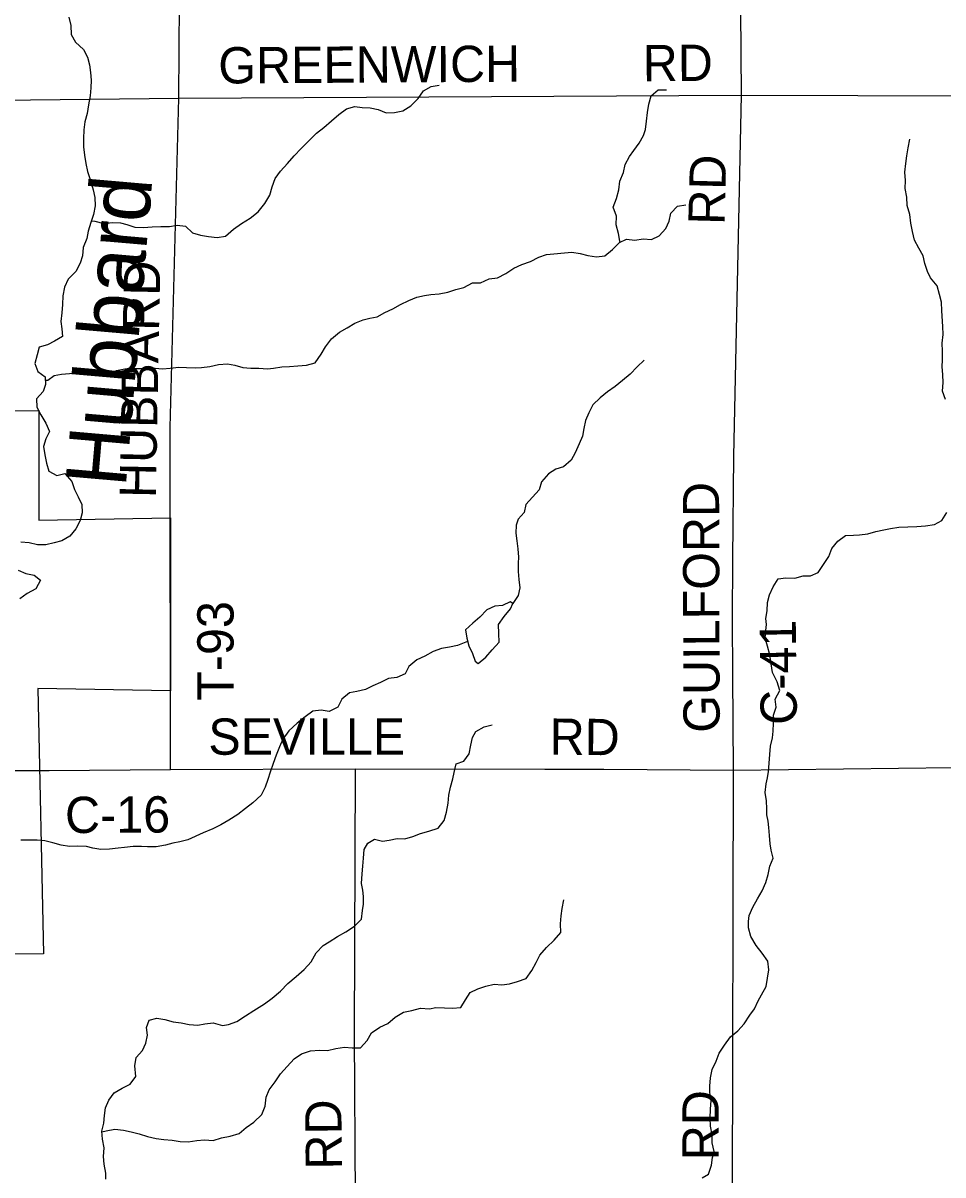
# Model space of a CAD drawing. Extents: x 1985906 to 2277390, y 930619 to 1324581.
# Drawn here: x 2146803 to 2154411, y 1093746 to 1103268 of the extents above; entities that cross this region are included whole.
import ezdxf

# ---------------------------------------------------------------- set-up
doc = ezdxf.new("R2010")
doc.units = 0
for name, color, linetype in [('GM_X_City_Street', 7, 'Continuous'), ('GM_X_Corporation', 7, 'Continuous'), ('GM_X_County_Road', 7, 'Continuous'), ('GM_X_County_Road_Text', 7, 'Continuous'), ('GM_X_Minor_Lake', 7, 'Continuous'), ('GM_X_Minor_River', 7, 'Continuous'), ('GM_X_Minor_River_Text', 7, 'Continuous'), ('GM_X_Township_Road', 7, 'Continuous'), ('GM_X_Township_Road_Text', 7, 'Continuous')]:
    doc.layers.add(name, color=color, linetype=linetype)

msp = doc.modelspace()

# ---------------------------------------------------------------- linework, layer by layer
at = {"layer": 'GM_X_City_Street'}
msp.add_lwpolyline([(2144906.3, 1097104.6), (2145782.8, 1097089), (2145830.7, 1097088.2), (2146944.6, 1097090.1), (2147019.2, 1097090.6)], dxfattribs=at)
at = {"layer": 'GM_X_Corporation'}
msp.add_lwpolyline([(2146630.7, 1100061.2), (2146933.1, 1100066.5), (2146933.1, 1099158.3), (2148022.9, 1099177.3), (2148022.9, 1097747.3), (2146924.6, 1097766.5), (2146973.3, 1095572.8), (2145031.8, 1095556.9)], dxfattribs=at)
at = {"layer": 'GM_X_County_Road'}
for points in [[(2152678.4, 1097092.6), (2152673.3, 1097881.4), (2152670.3, 1098337.9), (2152673.1, 1098838.5), (2152681.6, 1099687.5), (2152744, 1102670.9), (2152734.4, 1104084), (2152737.7, 1104462.8)], [(2145636.5, 1102618.6), (2148092.1, 1102646.5), (2152744, 1102670.9), (2157560, 1102659.5), (2158937.6, 1102692.5), (2161297.2, 1102684.6), (2161486.2, 1102684.9)], [(2147019.2, 1097090.6), (2148022.9, 1097097.3), (2149553.3, 1097103.6), (2151117.8, 1097100.1), (2151606, 1097099.4), (2152678.4, 1097092.6), (2156317.3, 1097135), (2156707.4, 1097137.6), (2156889.5, 1097136.8), (2157593.3, 1097149.9), (2159274.3, 1097152.9), (2159744.4, 1097158), (2160686.6, 1097174.4), (2161805, 1097183.9), (2162757.2, 1097196.3)]]:
    msp.add_lwpolyline(points, dxfattribs=at)
at = {"layer": 'GM_X_Minor_Lake'}
for points in [[(2150853.3, 1098471.1), (2150832.1, 1098484.6), (2150768.4, 1098453.7), (2150704.4, 1098448.9), (2150638.6, 1098418), (2150581.3, 1098357.2), (2150523.8, 1098308.4), (2150462.4, 1098251.6), (2150473.2, 1098183.6), (2150490, 1098119.7), (2150518.8, 1098057.9), (2150541.7, 1097992.1)], [(2150853.4, 1098471.1), (2150832.1, 1098484.6), (2150768.4, 1098453.7), (2150704.4, 1098448.9), (2150638.6, 1098418), (2150581.3, 1098357.2), (2150523.8, 1098308.4), (2150462.4, 1098251.6), (2150473.2, 1098183.6), (2150490, 1098119.7), (2150518.8, 1098057.9), (2150541.7, 1097992.1)], [(2150541.7, 1097992.1), (2150565.9, 1097974.4), (2150631.4, 1098027.3), (2150682.7, 1098088), (2150742, 1098150.9), (2150737.2, 1098222.9), (2150736.3, 1098295.1), (2150781.5, 1098361.7), (2150834.8, 1098426.5), (2150853.3, 1098471.1)], [(2150541.7, 1097992.1), (2150565.9, 1097974.4), (2150631.4, 1098027.3), (2150682.7, 1098088), (2150742, 1098150.9), (2150737.2, 1098222.9), (2150736.3, 1098295.1), (2150781.5, 1098361.7), (2150834.8, 1098426.5), (2150853.1, 1098470.8)]]:
    msp.add_lwpolyline(points, dxfattribs=at)
at = {"layer": 'GM_X_Minor_River'}
for points in [[(2147180.5, 1103316.9), (2147197, 1103246.9), (2147201.5, 1103172.8), (2147238, 1103108.9), (2147302.5, 1103049.2), (2147336.9, 1102987.4), (2147351.4, 1102923.3), (2147361.8, 1102859.3), (2147366.2, 1102797.2), (2147364.7, 1102733.1), (2147359.1, 1102666.9), (2147345.6, 1102592.7), (2147332, 1102520.5), (2147314.5, 1102452.3), (2147306.9, 1102384.1), (2147303.4, 1102314), (2147303.8, 1102243.8), (2147310.3, 1102175.8), (2147322.8, 1102107.7), (2147337.2, 1102041.7), (2147361.8, 1101965.8), (2147384.3, 1101889.8), (2147396.7, 1101825.8), (2147399.2, 1101757.6), (2147385.7, 1101685.4), (2147364.1, 1101619.2), (2147340.5, 1101548.9), (2147330.9, 1101486.7), (2147301.4, 1101412.4), (2147295.8, 1101344.2), (2147276.2, 1101282), (2147240.6, 1101213.6), (2147177, 1101151.1), (2147145.4, 1101084.8), (2147131.8, 1101012.6), (2147130.3, 1100940.4), (2147124.8, 1100872.3), (2147115.2, 1100800.1), (2147123.6, 1100740), (2147128.1, 1100675.9), (2147064.2, 1100639.5), (2147004.4, 1100609), (2146936.4, 1100588.5), (2146920.8, 1100524.3), (2146901.3, 1100454), (2146925.7, 1100388.1), (2146986.1, 1100342.4), (2146988.5, 1100280.3), (2146968.9, 1100222.1), (2146913.2, 1100161.6), (2146915.7, 1100093.5), (2146950.1, 1100029.6)], [(2147368.6, 1101633), (2147398.1, 1101629.4), (2147470.3, 1101609.9), (2147542.3, 1101620.4), (2147610.4, 1101616.8), (2147660.6, 1101603.1), (2147726.8, 1101579.5), (2147798.9, 1101578), (2147871, 1101582.5), (2147943, 1101585), (2148013.1, 1101585.5), (2148077.1, 1101597.9), (2148145.3, 1101588.3), (2148205.7, 1101532.6), (2148269.9, 1101515.1), (2148336.1, 1101503.5), (2148408.2, 1101495.9), (2148476.2, 1101506.4), (2148543.9, 1101565), (2148609.7, 1101611.5), (2148681.5, 1101654.1), (2148747.2, 1101708.6), (2148802.8, 1101775.1), (2148844.4, 1101845.5), (2148864, 1101913.7), (2148887.6, 1101984), (2148933.2, 1102044.4), (2148988.9, 1102106.9), (2149046.5, 1102169.4), (2149104.2, 1102229.9), (2149171.8, 1102300.5), (2149229.5, 1102359), (2149291.3, 1102403.4), (2149355, 1102460), (2149414.7, 1102512.5), (2149478.5, 1102559), (2149546.4, 1102577.5), (2149606.6, 1102569.8), (2149674.7, 1102566.3), (2149738.8, 1102552.7), (2149805.1, 1102525.1), (2149875.2, 1102529.6), (2149943.2, 1102542), (2150009, 1102584.6), (2150070.6, 1102643.1), (2150116.3, 1102707.5), (2150178.1, 1102744), (2150244.1, 1102754.4)], [(2151742.4, 1101457.6), (2151738.6, 1101464.2), (2151728.1, 1101528.2), (2151709.6, 1101600.2), (2151711.2, 1101672.4), (2151684.6, 1101746.3), (2151712.2, 1101818.6), (2151731.7, 1101888.9), (2151739.3, 1101961.1), (2151768.8, 1102031.4), (2151782.4, 1102099.6), (2151818, 1102163.9), (2151855.7, 1102214.3), (2151899.4, 1102274.7), (2151935, 1102339), (2151950.7, 1102389.2), (2151960.2, 1102457.4), (2151967.8, 1102527.6), (2151977.3, 1102597.8), (2151996.9, 1102666), (2152054.6, 1102716.5), (2152124.7, 1102714.9)], [(2154430.7, 1100155.9), (2154408.2, 1100225.9), (2154411.7, 1100298.1), (2154409.3, 1100360.1), (2154404.8, 1100430.2), (2154408.5, 1100480.4), (2154406, 1100554.5), (2154403.5, 1100622.6), (2154413.1, 1100694.8), (2154410.6, 1100760.9), (2154401.8, 1100889), (2154399.3, 1100961.1), (2154382.8, 1101023.1), (2154364.3, 1101095.1), (2154307.8, 1101162.9), (2154283.4, 1101214.8), (2154261, 1101280.8), (2154246.5, 1101344.8), (2154212.1, 1101406.6), (2154175.6, 1101474.5), (2154159.1, 1101544.5), (2154144.6, 1101614.6), (2154136.1, 1101686.6), (2154115.6, 1101758.6), (2154113.1, 1101828.7), (2154098.6, 1101900.7), (2154102.2, 1101966.9), (2154095.7, 1102035), (2154103.3, 1102107.1), (2154112.9, 1102171.3), (2154122.4, 1102237.5), (2154136, 1102307.7)], [(2146987.2, 1100315.7), (2147008.3, 1100316.5), (2147060.1, 1100354.9), (2147120.1, 1100365.4), (2147186.2, 1100371.8), (2147236.2, 1100374.1), (2147306.4, 1100366.6), (2147374.4, 1100377.1), (2147442.5, 1100367.5), (2147510.6, 1100364), (2147576.5, 1100396.5), (2147644.5, 1100408.9), (2147708.6, 1100411.4), (2147772.6, 1100411.8), (2147822.7, 1100414.1), (2147894.7, 1100416.6), (2147956.9, 1100409), (2148020.9, 1100415.5), (2148090.9, 1100424), (2148155, 1100420.4), (2148227.2, 1100416.9), (2148279.2, 1100421.2), (2148347.2, 1100429.7), (2148419.2, 1100444.2), (2148493.3, 1100450.7), (2148553.4, 1100441.1), (2148619.6, 1100421.5), (2148685.7, 1100413.9), (2148751.8, 1100414.4), (2148823.9, 1100410.8), (2148874, 1100415.2), (2148944, 1100425.7), (2149008, 1100430.1), (2149076.1, 1100434.6), (2149148.2, 1100439.1), (2149220.1, 1100459.6), (2149267.7, 1100530), (2149305.4, 1100590.4), (2149352.9, 1100658.8), (2149420.7, 1100713.4), (2149484.5, 1100749.9), (2149546.3, 1100788.3), (2149616.2, 1100814.9), (2149670.2, 1100829.2), (2149732.2, 1100839.7), (2149794.1, 1100874.1), (2149860, 1100904.6), (2149925.8, 1100941.1), (2149993.6, 1100975.7), (2150059.6, 1101002.1), (2150123.5, 1101016.6), (2150175.6, 1101023), (2150243.6, 1101029.4), (2150315.6, 1101043.9), (2150383.5, 1101064.4), (2150449.5, 1101080.9), (2150519.3, 1101119.4), (2150587.4, 1101119.9), (2150657.3, 1101152.4), (2150727.3, 1101162.9), (2150797.2, 1101197.4), (2150861, 1101241.9), (2150928.8, 1101272.4), (2150998.8, 1101296.9), (2151068.6, 1101333.5), (2151132.6, 1101353.9), (2151342.7, 1101373.4), (2151410.8, 1101363.8), (2151475, 1101346.2), (2151545.2, 1101334.7), (2151615.2, 1101343.2), (2151679, 1101395.7), (2151734.6, 1101454.1), (2151794.5, 1101480.6), (2151862.7, 1101473), (2151930.7, 1101483.5), (2152000.8, 1101478), (2152064.7, 1101508.4), (2152118.3, 1101570.9), (2152146, 1101631.2), (2152161.6, 1101697.4), (2152215.2, 1101753.9), (2152285.3, 1101766.4)], [(2151939.4, 1100481.8), (2151881.7, 1100427.3), (2151824, 1100366.9), (2151760.2, 1100314.3), (2151700.5, 1100263.9), (2151636.7, 1100219.3), (2151575, 1100170.9), (2151515.3, 1100112.3), (2151481.7, 1100046), (2151456.1, 1099981.7), (2151440.5, 1099915.5), (2151428.9, 1099853.3), (2151401.3, 1099789), (2151369.7, 1099716.7), (2151336.1, 1099654.4), (2151272.4, 1099599.8), (2151210.4, 1099579.4), (2151148.6, 1099542.9), (2151091, 1099474.4), (2151071.4, 1099410.2), (2151015.8, 1099347.7), (2150960.1, 1099287.2), (2150948.5, 1099223), (2150896.8, 1099166.6), (2150881.1, 1099116.4), (2150879.5, 1099052.3), (2150888, 1098988.2), (2150894.4, 1098922.1), (2150900.9, 1098854.1), (2150899.2, 1098803.9), (2150897.7, 1098733.8), (2150904.1, 1098667.8), (2150910.6, 1098599.7), (2150897, 1098535.5), (2150853.4, 1098471.1)], [(2146950.1, 1100029.6), (2146990.7, 1099961.8), (2147023.2, 1099891.9), (2146991.5, 1099831.6), (2146971.9, 1099767.3), (2146982.4, 1099699.3), (2146996.9, 1099629.2), (2147017.3, 1099563.3), (2147083.7, 1099527.7), (2147149.6, 1099544.1), (2147206.1, 1099478.4), (2147228.6, 1099412.4), (2147259, 1099352.5), (2147289.5, 1099288.6), (2147292, 1099218.5), (2147276.4, 1099156.3), (2147240.8, 1099085.9), (2147191.1, 1099025.5), (2147123.3, 1098989), (2147059.3, 1098970.5), (2146991.4, 1098954), (2146923.3, 1098953.6), (2146853.1, 1098971.1), (2146784.9, 1098976.7)], [(2153857.2, 1099066.2), (2153921.2, 1099078.7), (2153977.2, 1099091.1), (2154047.2, 1099099.6), (2154121.3, 1099104.1), (2154195.3, 1099106.6), (2154267.4, 1099111.1), (2154341.4, 1099121.6), (2154401.3, 1099156), (2154442.9, 1099222.4)], [(2152418.9, 1093721.3), (2152472.8, 1093751.7), (2152496.3, 1093826), (2152503.9, 1093890.2), (2152517.6, 1093940.4), (2152501.1, 1094010.4), (2152502.7, 1094076.5), (2152488.2, 1094148.5), (2152485.7, 1094216.6), (2152487.2, 1094288.8), (2152494.8, 1094360.9), (2152484.3, 1094429), (2152481.9, 1094481.1), (2152487.5, 1094549.2), (2152503.1, 1094617.4), (2152534.6, 1094685.8), (2152560.2, 1094752.1), (2152603.9, 1094818.5), (2152653.5, 1094886.9), (2152713.2, 1094937.4), (2152766.9, 1094995.9), (2152814.5, 1095066.3), (2152852.1, 1095120.7), (2152883.8, 1095185), (2152911.5, 1095235.2), (2152949.1, 1095303.6), (2152960.6, 1095371.8), (2152972.2, 1095442), (2152963.7, 1095512.1), (2152915.2, 1095579.9), (2152866.7, 1095643.7), (2152822.1, 1095717.5), (2152803.6, 1095789.5), (2152803.3, 1095841.6), (2152809, 1095891.7), (2152838.5, 1095960), (2152876.1, 1096028.4), (2152915.8, 1096094.8), (2152945.3, 1096163.1), (2152964.9, 1096229.3), (2152980.5, 1096297.6), (2153008.1, 1096365.9), (2152989.6, 1096431.8), (2152981.3, 1096483.9), (2152976.8, 1096552), (2152972.3, 1096618.1), (2152966, 1096670.1), (2152955.6, 1096722.1), (2152955.3, 1096772.2), (2152950.9, 1096838.3), (2152940.4, 1096908.3), (2152947.9, 1096978.5), (2152959.6, 1097028.7), (2152967.3, 1097080.8), (2152974.8, 1097151), (2152980.3, 1097223.1), (2152985.9, 1097289.3), (2153001.5, 1097359.5), (2153007.1, 1097415.7), (2153010.7, 1097479.8), (2153008.2, 1097547.9), (2153031.8, 1097614.2), (2153023.4, 1097678.2), (2153062.9, 1097750.6), (2153040.4, 1097822.6), (2153001.9, 1097898.5), (2152991.4, 1097972.5), (2152978.9, 1098046.6), (2152960.4, 1098116.6), (2152939.9, 1098182.5), (2152947.5, 1098246.7), (2152951.2, 1098296.8), (2152946.8, 1098346.9), (2152956.4, 1098409.1), (2152960, 1098477.2), (2152977.6, 1098541.4), (2153007.2, 1098607.7), (2153048.8, 1098674.1), (2153112.8, 1098682.6), (2153184.9, 1098679.1), (2153254.9, 1098699.6), (2153314.9, 1098697.9), (2153378.8, 1098726.4), (2153424.4, 1098792.8), (2153468.1, 1098859.2), (2153491.7, 1098923.5), (2153541.3, 1098986), (2153605.1, 1099032.5), (2153671.1, 1099034.9), (2153721.2, 1099037.3), (2153789.2, 1099045.7), (2153857.2, 1099066.2)], [(2146762.5, 1098744.1), (2146826.7, 1098718.5), (2146894.9, 1098702.9), (2146947.2, 1098663.2), (2146909.7, 1098590.8), (2146835.8, 1098552.3), (2146776.1, 1098509.8)], [(2150479.8, 1098156.1), (2150397.1, 1098121.4), (2150329.1, 1098108.9), (2150263.1, 1098098.5), (2150195.2, 1098072), (2150125.4, 1098033.4), (2150059.5, 1098002.9), (2149993.8, 1097950.4), (2149962.2, 1097888.1), (2149894.3, 1097859.6), (2149826.2, 1097851.1), (2149760.4, 1097816.6), (2149696.5, 1097790.1), (2149634.6, 1097759.7), (2149564.6, 1097741.2), (2149502.6, 1097732.7), (2149440.9, 1097680.2), (2149405.3, 1097613.9), (2149333.4, 1097577.3), (2149267.3, 1097588.9), (2149199.3, 1097580.4), (2149135.5, 1097533.9), (2149069.8, 1097479.4), (2149002.1, 1097416.8), (2148952.5, 1097348.4), (2148922.9, 1097286.1), (2148895.3, 1097215.8), (2148871.7, 1097147.5), (2148846.2, 1097075.2), (2148826.6, 1097015), (2148805, 1096950.7), (2148771.3, 1096886.4), (2148703.7, 1096821.8), (2148641.9, 1096775.3), (2148578.2, 1096726.8), (2148504.4, 1096680.2), (2148438.6, 1096639.7), (2148372.7, 1096607.2), (2148292.8, 1096574.6), (2148167, 1096517.7), (2148101.1, 1096499.2), (2148043.1, 1096488.8), (2147981.1, 1096472.4), (2147903.1, 1096457.8), (2147833, 1096457.3), (2147782.9, 1096461), (2147714.8, 1096462.6), (2147640.8, 1096452), (2147588.8, 1096447.7), (2147518.8, 1096439.2), (2147446.7, 1096436.7), (2147380.5, 1096448.3), (2147328.4, 1096460), (2147256.3, 1096463.5), (2147186.2, 1096461), (2147118, 1096472.6), (2147049.8, 1096492.2), (2146983.6, 1096507.7), (2146919.5, 1096513.3), (2146849.4, 1096512.8), (2146785.4, 1096514.4)], [(2147488.9, 1093712.3), (2147486.5, 1093762.3), (2147474, 1093834.4), (2147467.6, 1093898.5), (2147475.1, 1093970.6), (2147460.7, 1094040.7), (2147454.2, 1094108.7), (2147471.8, 1094175), (2147475.4, 1094237.1), (2147484.9, 1094301.3), (2147512.6, 1094365.6), (2147556.2, 1094426), (2147622, 1094464.5), (2147687.9, 1094497), (2147735.5, 1094559.4), (2147728.9, 1094647.5), (2147738.5, 1094717.7), (2147790.2, 1094776.1), (2147817.8, 1094836.4), (2147833.4, 1094902.6), (2147825, 1094964.7), (2147846.6, 1095024.9), (2147908.6, 1095041.4), (2147976.7, 1095031.8), (2148044.9, 1095012.3), (2148111.1, 1095002.7), (2148177.2, 1094991.1), (2148247.4, 1094983.6), (2148305.3, 1094996), (2148375.4, 1095002.5), (2148451.6, 1094982.9), (2148501.6, 1094989.3), (2148571.6, 1095013.8), (2148643.3, 1095060.4), (2148711.1, 1095104.9), (2148798.9, 1095159.6), (2148864.6, 1095208.1), (2148932.3, 1095264.6), (2148992, 1095329.1), (2149061.7, 1095385.7), (2149127.4, 1095444.3), (2149187, 1095508.8), (2149228.6, 1095581.2), (2149284.2, 1095643.7), (2149336.1, 1095674.1), (2149403.9, 1095716.6), (2149473.7, 1095755.1), (2149543.5, 1095803.7), (2149603.2, 1095860.2), (2149610.7, 1095932.3), (2149618.4, 1095984.5), (2149620, 1096048.6), (2149613.6, 1096100.6), (2149603.2, 1096156.7), (2149608.7, 1096234.9), (2149614.3, 1096299), (2149617.9, 1096365.1), (2149623.4, 1096435.3), (2149655.1, 1096487.6), (2149710.9, 1096522), (2149777.1, 1096506.5), (2149831.1, 1096514.8), (2149897.1, 1096527.3), (2149961.2, 1096525.7), (2150027.2, 1096544.2), (2150091.1, 1096568.7), (2150159, 1096589.1), (2150237, 1096613.7), (2150286.6, 1096676.2), (2150306.2, 1096744.4), (2150319.7, 1096818.6), (2150323.3, 1096886.8), (2150336.9, 1096951), (2150358.4, 1097021.2), (2150368.1, 1097073.4), (2150385.6, 1097143.6), (2150449.6, 1097166.1), (2150493.2, 1097228.5), (2150506.7, 1097298.7), (2150520.3, 1097362.9), (2150548, 1097413.2), (2150615.9, 1097451.7), (2150683.8, 1097468.2)], [(2147454.9, 1094101.7), (2147490.2, 1094111), (2147562.2, 1094125.5), (2147634.4, 1094116), (2147698.5, 1094102.4), (2147762.7, 1094084.8), (2147833, 1094065.2), (2147903.2, 1094047.6), (2147967.3, 1094038.1), (2148035.4, 1094032.5), (2148103.6, 1094022.9), (2148169.7, 1094019.4), (2148239.7, 1094029.9), (2148303.7, 1094036.3), (2148375.9, 1094030.8), (2148443.8, 1094053.3), (2148515.8, 1094065.8), (2148589.7, 1094088.3), (2148649.5, 1094138.8), (2148711.3, 1094183.3), (2148776.9, 1094245.8), (2148804.5, 1094316.1), (2148814, 1094390.3), (2148837.6, 1094450.6), (2148887.2, 1094517.1), (2148932.9, 1094581.5), (2148986.5, 1094643.9), (2149044.2, 1094706.4), (2149106, 1094746.9), (2149179.9, 1094771.4), (2149254, 1094778), (2149320.1, 1094774.4), (2149390, 1094790.9), (2149462.1, 1094803.4), (2149526.2, 1094797.8), (2149594.3, 1094796.3), (2149649.9, 1094856.7), (2149685.5, 1094921.1), (2149753.3, 1094967.6), (2149819.2, 1094998.1), (2149880.9, 1095050.6), (2149950.7, 1095091.2), (2150018.7, 1095105.6), (2150090.7, 1095126.2), (2150164.8, 1095120.6), (2150216.8, 1095129), (2150288.9, 1095127.5), (2150355, 1095123.9), (2150423.1, 1095130.4), (2150462.7, 1095194.8), (2150500.3, 1095253.1), (2150564.2, 1095285.6), (2150630.2, 1095306.1), (2150698.1, 1095324.6), (2150762.3, 1095317), (2150826.3, 1095325.4), (2150892.2, 1095345.9), (2150964.1, 1095370.4), (2151011.8, 1095436.9), (2151047.4, 1095501.2), (2151077, 1095563.5), (2151132.7, 1095626), (2151194.3, 1095686.5), (2151252, 1095749), (2151247.5, 1095821.1), (2151253.1, 1095889.3), (2151262.7, 1095949.4), (2151276.2, 1096021.7)]]:
    msp.add_lwpolyline(points, dxfattribs=at)
at = {"layer": 'GM_X_Township_Road'}
for points in [[(2148092.1, 1102646.5), (2148112.1, 1105426)], [(2148019.7, 1099172.2), (2148018.5, 1099924.5), (2148092.1, 1102646.5)], [(2148021.8, 1097771.7), (2148019.7, 1099172.2)], [(2148022.9, 1097097.3), (2148021.8, 1097771.7)], [(2149569, 1090470.2), (2149552.4, 1093551.6), (2149545.6, 1094901.1), (2149553.3, 1097103.6)], [(2152684.1, 1089315.7), (2152670.1, 1090039.8), (2152671.2, 1093576.6), (2152678.4, 1097092.6)]]:
    msp.add_lwpolyline(points, dxfattribs=at)

# ---------------------------------------------------------------- texts
at = {"layer": 'GM_X_County_Road_Text'}
for s, rotation, p in [('GREENWICH', 0.34402, (2148418.6, 1102768.2)), ('RD', 0.49366, (2151929.5, 1102785.7)), ('RD', 88.51743, (2152604.4, 1101597.2)), ('GUILFORD', 90.13664, (2152564.7, 1097401.9)), ('C-41', 90.68652, (2153204, 1097468.3)), ('SEVILLE', 0.00001, (2148335.7, 1097219.8)), ('RD', 359.50684, (2151157.3, 1097219.8)), ('C-16', 0.3429, (2147150.8, 1096571.8))]:
    msp.add_text(s, height=300, rotation=rotation, dxfattribs=at).set_placement(p)
at = {"layer": 'GM_X_Minor_River_Text'}
msp.add_text('Hubbard', height=500.24, rotation=85.04516, dxfattribs=at).set_placement((2147651.5, 1099423.4))
at = {"layer": 'GM_X_Township_Road_Text'}
for s, rotation, p in [('HUBBARD', 88.87769, (2147900.7, 1099339.8)), ('T-93', 90, (2148544, 1097665)), ('RD', 90, (2152556, 1093867.8)), ('RD', 90.49365, (2149440.2, 1093792))]:
    msp.add_text(s, height=300, rotation=rotation, dxfattribs=at).set_placement(p)

doc.saveas('drawing.dxf')
